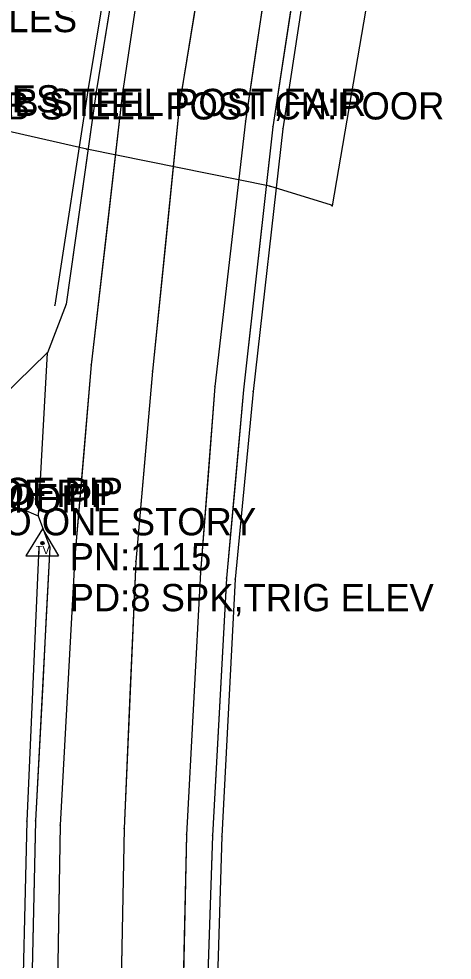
# Model space of a CAD drawing. Extents: x -99999 to 591807, y -99999 to 347168.
# Drawn here: x 591063.4 to 591143, y 322005.6 to 322178.3 of the extents above; entities that cross this region are included whole.
import ezdxf

# ---------------------------------------------------------------- set-up
doc = ezdxf.new("R2010")
doc.units = 0
for name, color, linetype in [('S_BREAKLINE', 7, 'Continuous'), ('S_DRIVEWAY', 7, 'Continuous'), ('S_EDGE_PAVEMENT', 7, 'Continuous'), ('S_FENCE_ANNOT', 7, 'Continuous'), ('S_GRD_PT_SYM', 7, 'Continuous'), ('S_PAVEMENT_CROWN', 7, 'Continuous'), ('S_RDW_PT_SYM', 7, 'Continuous'), ('S_SECONDARY_CTL', 7, 'Continuous'), ('S_SECONDARY_CTL_ANNOT', 7, 'Continuous'), ('S_SHOULDER', 7, 'Continuous'), ('S_SIDE_DRAIN_ANNOT', 7, 'Continuous'), ('S_SURVEY_TEXT_ANNOT', 7, 'Continuous'), ('S_UTILITY_POLE_ANNOT', 7, 'Continuous'), ('S_UTL_PT_SYM', 7, 'Continuous'), ('S_WATER_UTILITIES', 7, 'Continuous')]:
    doc.layers.add(name, color=color, linetype=linetype)

msp = doc.modelspace()

# ---------------------------------------------------------------- linework, layer by layer
at = {"layer": 'S_BREAKLINE'}
for points in [[(591141.79, 322332.97), (591141.12, 322331.79), (591136.59, 322308.68), (591127.43, 322256.21), (591119.53, 322208.24), (591111.89, 322158.15), (591106.46, 322109.92), (591103.16, 322075.48), (591100.72, 322028.3), (591099.37, 321984.38), (591097.36, 321936.25)], [(591093.81, 322271.33), (591084.18, 322214.09), (591076.06, 322165.17), (591070.01, 322125.75)], [(591068.65, 322117.01), (591066.95, 322087.14)], [(591067.08, 322081.38), (591064.9, 322031.1), (591063.85, 321987.78), (591065.77, 321933.53), (591065.95, 321923.68)]]:
    msp.add_lwpolyline(points, dxfattribs=at)
at = {"layer": 'S_DRIVEWAY'}
msp.add_lwpolyline([(591068.65, 322117.01), (591054.64, 322103.44), (591053.56, 322090.23), (591063.83, 322088.44), (591066.95, 322087.12), (591069.12, 322081.36)], dxfattribs=at)
msp.add_lwpolyline([(591068.65, 322117.01), (591054.64, 322103.44), (591053.56, 322090.23), (591063.83, 322088.44), (591066.95, 322087.12), (591069.12, 322081.36)], dxfattribs=at)
at = {"layer": 'S_EDGE_PAVEMENT'}
for points in [[(591155.01, 322516.17), (591143.09, 322467.79), (591137.43, 322444.09), (591127.36, 322400.1), (591119.29, 322363.42), (591113.95, 322339.18), (591109.05, 322315.77), (591098.43, 322263.26), (591089.75, 322213.36), (591082.38, 322164.3), (591076.73, 322114.81), (591073.7, 322079.67), (591071, 322030.35), (591070.29, 321986.98), (591070.69, 321935.66), (591071.05, 321919.08)], [(591177.24, 322510.33), (591165.63, 322463.26), (591159.78, 322438.95), (591149.6, 322395.03), (591141.62, 322358.52), (591136.41, 322334.23), (591131.46, 322310.28), (591121.02, 322257.9), (591112.47, 322209.78), (591105.04, 322159.54), (591099.44, 322110.84), (591096.78, 322076.76), (591094.19, 322028.58), (591093.31, 321985.65), (591093.42, 321935.97), (591093.55, 321920.04)], [(591086.07, 322188.83), (591082.38, 322164.3), (591079.55, 322139.56), (591076.73, 322114.81), (591075.22, 322097.24), (591073.7, 322079.67), (591072.35, 322055.01), (591071, 322030.35), (591070.64, 322008.66), (591070.29, 321986.98), (591070.39, 321974.15), (591070.49, 321961.32), (591070.59, 321948.49), (591070.69, 321935.66), (591071.05, 321919.08)], [(591108.76, 322184.66), (591106.9, 322172.1), (591105.04, 322159.54), (591102.24, 322135.19), (591099.44, 322110.84), (591098.11, 322093.8), (591096.78, 322076.76), (591095.48, 322052.67), (591094.19, 322028.58), (591093.75, 322007.12), (591093.31, 321985.65), (591093.37, 321960.81), (591093.42, 321935.97), (591093.55, 321920.04)]]:
    msp.add_lwpolyline(points, dxfattribs=at)
at = {"layer": 'S_GRD_PT_SYM'}
for points in [[(591076.06, 322165.17), (591076.11, 322165.16), (591076.06, 322165.17), (591076.07, 322165.21), (591076.06, 322165.17), (591076.02, 322165.17), (591076.06, 322165.17), (591076.06, 322165.12)], [(591111.89, 322158.15), (591111.93, 322158.15), (591111.89, 322158.15), (591111.89, 322158.2), (591111.89, 322158.15), (591111.84, 322158.16), (591111.89, 322158.15), (591111.88, 322158.1)], [(591070.01, 322125.75), (591070.06, 322125.74), (591070.01, 322125.75), (591070.02, 322125.79), (591070.01, 322125.75), (591069.96, 322125.75), (591070.01, 322125.75), (591070, 322125.7)], [(591068.65, 322117.01), (591068.7, 322117.01), (591068.65, 322117.01), (591068.65, 322117.06), (591068.65, 322117.01), (591068.6, 322117.02), (591068.65, 322117.01), (591068.65, 322116.96)], [(591106.46, 322109.92), (591106.51, 322109.91), (591106.46, 322109.92), (591106.46, 322109.97), (591106.46, 322109.92), (591106.41, 322109.92), (591106.46, 322109.92), (591106.46, 322109.87)], [(591066.95, 322087.14), (591067, 322087.14), (591066.95, 322087.14), (591066.95, 322087.19), (591066.95, 322087.14), (591066.9, 322087.14), (591066.95, 322087.14), (591066.95, 322087.09)], [(591067.08, 322081.38), (591067.13, 322081.38), (591067.08, 322081.38), (591067.09, 322081.43), (591067.08, 322081.38), (591067.03, 322081.38), (591067.08, 322081.38), (591067.08, 322081.33)], [(591103.16, 322075.48), (591103.21, 322075.48), (591103.16, 322075.48), (591103.16, 322075.53), (591103.16, 322075.48), (591103.11, 322075.48), (591103.16, 322075.48), (591103.16, 322075.43)], [(591064.9, 322031.1), (591064.95, 322031.1), (591064.9, 322031.1), (591064.91, 322031.15), (591064.9, 322031.1), (591064.85, 322031.11), (591064.9, 322031.1), (591064.9, 322031.05)], [(591100.72, 322028.3), (591100.77, 322028.3), (591100.72, 322028.3), (591100.72, 322028.35), (591100.72, 322028.3), (591100.67, 322028.3), (591100.72, 322028.3), (591100.72, 322028.25)]]:
    msp.add_lwpolyline(points, close=True, dxfattribs=at)
at = {"layer": 'S_PAVEMENT_CROWN'}
for points in [[(591166.02, 322513.49), (591154.15, 322465.35), (591148.44, 322441.45), (591138.39, 322397.64), (591130.1, 322360.67), (591124.85, 322336.77), (591119.75, 322312.64), (591109.15, 322260.48), (591100.94, 322212.04), (591092.95, 322162.74), (591087.94, 322113.64), (591084.9, 322078.73), (591082.75, 322029.75), (591081.89, 321986.1), (591081.86, 321935.1), (591082.15, 321919.25)], [(591096.94, 322187.39), (591092.95, 322162.74), (591090.45, 322138.19), (591087.94, 322113.64), (591086.42, 322096.18), (591084.9, 322078.73), (591083.82, 322054.24), (591082.75, 322029.75), (591082.32, 322007.92), (591081.89, 321986.1), (591081.88, 321973.35), (591081.88, 321960.6), (591081.87, 321947.85), (591081.86, 321935.1), (591082.15, 321919.25)]]:
    msp.add_lwpolyline(points, dxfattribs=at)
at = {"layer": 'S_RDW_PT_SYM'}
for points in [[(591077.61, 322164.92), (591077.66, 322164.91), (591077.61, 322164.92), (591077.61, 322164.97), (591077.61, 322164.92), (591077.56, 322164.93), (591077.61, 322164.92), (591077.6, 322164.87)], [(591082.38, 322164.3), (591082.43, 322164.29), (591082.38, 322164.3), (591082.38, 322164.35), (591082.38, 322164.3), (591082.33, 322164.31), (591082.38, 322164.3), (591082.37, 322164.25)], [(591092.95, 322162.74), (591093, 322162.73), (591092.95, 322162.74), (591092.95, 322162.79), (591092.95, 322162.74), (591092.9, 322162.74), (591092.95, 322162.74), (591092.94, 322162.69)], [(591105.04, 322159.54), (591105.09, 322159.54), (591105.04, 322159.54), (591105.05, 322159.59), (591105.04, 322159.54), (591104.99, 322159.55), (591105.04, 322159.54), (591105.04, 322159.5)], [(591110.08, 322158.52), (591110.13, 322158.51), (591110.08, 322158.52), (591110.08, 322158.57), (591110.08, 322158.52), (591110.03, 322158.52), (591110.08, 322158.52), (591110.07, 322158.47)], [(591072.14, 322125.92), (591072.18, 322125.9), (591072.14, 322125.92), (591072.16, 322125.96), (591072.14, 322125.92), (591072.09, 322125.94), (591072.14, 322125.92), (591072.12, 322125.87)], [(591068.66, 322117.04), (591068.7, 322117.03), (591068.66, 322117.04), (591068.67, 322117.09), (591068.66, 322117.04), (591068.61, 322117.06), (591068.66, 322117.04), (591068.64, 322117)], [(591068.65, 322117.01), (591068.68, 322116.98), (591068.65, 322117.01), (591068.69, 322117.05), (591068.65, 322117.01), (591068.62, 322117.05), (591068.65, 322117.01), (591068.61, 322116.98)], [(591076.73, 322114.81), (591076.78, 322114.81), (591076.73, 322114.81), (591076.73, 322114.86), (591076.73, 322114.81), (591076.68, 322114.81), (591076.73, 322114.81), (591076.72, 322114.76)], [(591087.94, 322113.64), (591087.99, 322113.63), (591087.94, 322113.64), (591087.95, 322113.69), (591087.94, 322113.64), (591087.89, 322113.64), (591087.94, 322113.64), (591087.94, 322113.59)], [(591099.44, 322110.84), (591099.49, 322110.84), (591099.44, 322110.84), (591099.45, 322110.89), (591099.44, 322110.84), (591099.39, 322110.84), (591099.44, 322110.84), (591099.44, 322110.79)], [(591104.71, 322110.25), (591104.76, 322110.24), (591104.71, 322110.25), (591104.72, 322110.3), (591104.71, 322110.25), (591104.66, 322110.25), (591104.71, 322110.25), (591104.71, 322110.2)], [(591063.83, 322088.44), (591063.85, 322088.49), (591063.83, 322088.44), (591063.78, 322088.46), (591063.83, 322088.44), (591063.81, 322088.4), (591063.83, 322088.44), (591063.87, 322088.42)], [(591066.95, 322087.12), (591067, 322087.14), (591066.95, 322087.12), (591066.93, 322087.17), (591066.95, 322087.12), (591066.9, 322087.1), (591066.95, 322087.12), (591066.97, 322087.07)], [(591069.12, 322081.38), (591069.17, 322081.38), (591069.12, 322081.38), (591069.13, 322081.43), (591069.12, 322081.38), (591069.07, 322081.39), (591069.12, 322081.38), (591069.12, 322081.33)], [(591069.12, 322081.36), (591069.17, 322081.38), (591069.12, 322081.36), (591069.1, 322081.41), (591069.12, 322081.36), (591069.07, 322081.35), (591069.12, 322081.36), (591069.14, 322081.32)], [(591073.7, 322079.67), (591073.75, 322079.66), (591073.7, 322079.67), (591073.71, 322079.72), (591073.7, 322079.67), (591073.65, 322079.67), (591073.7, 322079.67), (591073.7, 322079.62)], [(591084.9, 322078.73), (591084.95, 322078.73), (591084.9, 322078.73), (591084.9, 322078.78), (591084.9, 322078.73), (591084.85, 322078.73), (591084.9, 322078.73), (591084.9, 322078.68)], [(591096.78, 322076.76), (591096.83, 322076.75), (591096.78, 322076.76), (591096.78, 322076.81), (591096.78, 322076.76), (591096.73, 322076.76), (591096.78, 322076.76), (591096.78, 322076.71)], [(591101.57, 322075.67), (591101.62, 322075.67), (591101.57, 322075.67), (591101.58, 322075.72), (591101.57, 322075.67), (591101.52, 322075.68), (591101.57, 322075.67), (591101.57, 322075.62)], [(591066.47, 322031.16), (591066.52, 322031.16), (591066.47, 322031.16), (591066.47, 322031.21), (591066.47, 322031.16), (591066.42, 322031.16), (591066.47, 322031.16), (591066.47, 322031.11)], [(591071, 322030.35), (591071.05, 322030.34), (591071, 322030.35), (591071, 322030.4), (591071, 322030.35), (591070.95, 322030.35), (591071, 322030.35), (591070.99, 322030.3)], [(591082.75, 322029.75), (591082.8, 322029.75), (591082.75, 322029.75), (591082.75, 322029.8), (591082.75, 322029.75), (591082.7, 322029.75), (591082.75, 322029.75), (591082.75, 322029.7)], [(591094.19, 322028.58), (591094.24, 322028.58), (591094.19, 322028.58), (591094.19, 322028.63), (591094.19, 322028.58), (591094.14, 322028.59), (591094.19, 322028.58), (591094.18, 322028.53)], [(591098.96, 322028.42), (591099.01, 322028.42), (591098.96, 322028.42), (591098.96, 322028.47), (591098.96, 322028.42), (591098.91, 322028.43), (591098.96, 322028.42), (591098.96, 322028.37)]]:
    msp.add_lwpolyline(points, close=True, dxfattribs=at)
at = {"layer": 'S_SECONDARY_CTL'}
for p, q in [((591067.74, 322084.71), (591064.73, 322079.75)), ((591067.74, 322084.71), (591070.69, 322079.75)), ((591064.73, 322079.75), (591070.69, 322079.75))]:
    msp.add_line(p, q, dxfattribs=at)
for radius in [0.311, 0.183, 0.103]:
    msp.add_circle((591067.74, 322082.1), radius, dxfattribs=at)
at = {"layer": 'S_SHOULDER'}
for points in [[(591137.44, 322469.34), (591133.63, 322445.25), (591123.61, 322401.4), (591115.17, 322364.04), (591109.62, 322340), (591104.84, 322316.87), (591100.55, 322301.53), (591098.37, 322297.55), (591094.49, 322275.99), (591096.67, 322271.91), (591095.47, 322264.19), (591085.55, 322213.88), (591077.61, 322164.92), (591072.14, 322125.92), (591068.66, 322117.04)], [(591137.44, 322469.34), (591133.63, 322445.25), (591128.62, 322423.33), (591123.61, 322401.4), (591119.39, 322382.72), (591115.17, 322364.04), (591109.62, 322340), (591104.84, 322316.87), (591100.55, 322301.53), (591098.37, 322297.55), (591094.49, 322275.99), (591096.67, 322271.91), (591095.47, 322264.19), (591092.99, 322251.61), (591090.51, 322239.04), (591088.03, 322226.46), (591085.55, 322213.88), (591081.58, 322189.4), (591077.61, 322164.92), (591074.87, 322145.42), (591072.14, 322125.92), (591068.66, 322117.04)], [(591140.98, 322334.12), (591140.11, 322333.4), (591135.06, 322309.16), (591125.66, 322256.81), (591117.7, 322208.32), (591110.08, 322158.52), (591104.71, 322110.25), (591101.57, 322075.67), (591098.96, 322028.42), (591097.53, 321984.9), (591096.04, 321935.78), (591096.53, 321921.92), (591094.98, 321920.21)], [(591113.89, 322183.42), (591111.98, 322170.97), (591110.08, 322158.52), (591107.39, 322134.38), (591104.71, 322110.25), (591103.14, 322092.96), (591101.57, 322075.67), (591100.27, 322052.05), (591098.96, 322028.42), (591098.25, 322006.66), (591097.53, 321984.9), (591096.79, 321960.34), (591096.04, 321935.78), (591096.53, 321921.92), (591094.98, 321920.21)], [(591069.12, 322081.38), (591066.47, 322031.16), (591065.51, 321987.43), (591066.83, 321935.11), (591068.74, 321922.89), (591069.66, 321919.06)], [(591069.12, 322081.38), (591068.46, 322068.83), (591067.8, 322056.27), (591067.13, 322043.72), (591066.47, 322031.16), (591065.99, 322009.3), (591065.51, 321987.43), (591065.84, 321974.35), (591066.17, 321961.27), (591066.5, 321948.19), (591066.83, 321935.11), (591068.74, 321922.89), (591069.66, 321919.06)]]:
    msp.add_lwpolyline(points, dxfattribs=at)
at = {"layer": 'S_UTL_PT_SYM'}
for points in [[(591075.88, 322154.39), (591075.88, 322154.44), (591075.88, 322154.39), (591075.83, 322154.39), (591075.88, 322154.39), (591075.88, 322154.34), (591075.88, 322154.39), (591075.93, 322154.39)], [(591109.5, 322147.63), (591109.5, 322147.68), (591109.5, 322147.63), (591109.45, 322147.63), (591109.5, 322147.63), (591109.5, 322147.58), (591109.5, 322147.63), (591109.55, 322147.63)], [(591120.85, 322144.09), (591120.85, 322144.14), (591120.85, 322144.09), (591120.8, 322144.09), (591120.85, 322144.09), (591120.85, 322144.04), (591120.85, 322144.09), (591120.9, 322144.09)], [(591120.97, 322143.98), (591120.97, 322144.03), (591120.97, 322143.98), (591120.92, 322143.98), (591120.97, 322143.98), (591120.97, 322143.93), (591120.97, 322143.98), (591121.02, 322143.98)]]:
    msp.add_lwpolyline(points, dxfattribs=at)
at = {"layer": 'S_WATER_UTILITIES'}
for p, q in [((591144.96, 322284.3), (591120.97, 322143.98)), ((591075.88, 322154.39), (591054.1, 322159.37)), ((591109.5, 322147.63), (591075.88, 322154.39)), ((591120.85, 322144.09), (591109.5, 322147.63))]:
    msp.add_line(p, q, dxfattribs=at)

# ---------------------------------------------------------------- texts
at = {"layer": 'S_FENCE_ANNOT'}
for s, p in [('6 BARB STEEL POST,FAIR', (591043.25, 322160.47)), ('4 BARB STEEL POST CN:POOR', (591041.64, 322159.84))]:
    msp.add_text(s, height=5, dxfattribs=at).set_placement(p)
at = {"layer": 'S_SECONDARY_CTL'}
msp.add_text('TV', height=1.5, rotation=360, dxfattribs=at).set_placement((591066.53, 322080.09))
at = {"layer": 'S_SECONDARY_CTL_ANNOT'}
for s, p in [('PN:1115', (591072.74, 322077.1)), ('PD:8 SPK,TRIG ELEV', (591072.74, 322069.6))]:
    msp.add_text(s, height=5, dxfattribs=at).set_placement(p)
at = {"layer": 'S_SIDE_DRAIN_ANNOT'}
for s, p in [('DI:16" TY:RCP CN:30% BTTM OF PI', (590967.9, 322087.96)), ('DI:16" TY:RCP CN:0% BTTM OF PIP', (590969.5, 322088.73)), ('DI:16" TY:RCP CN:0% BTTM OF PIP', (590970.94, 322089.1)), ('DI:16" TY:RCP CN:%FILL BTTM OF ', (590966.69, 322087.7))]:
    msp.add_text(s, height=5, dxfattribs=at).set_placement(p)
at = {"layer": 'S_SURVEY_TEXT_ANNOT'}
msp.add_text('BROKEN ASPH TO ONE STORY', height=5, dxfattribs=at).set_placement((591006.33, 322083.53))
at = {"layer": 'S_UTILITY_POLE_ANNOT'}
for s, p in [('2 POLES', (591046.24, 322175.86)), ('2 WIRES', (591043.54, 322161.13))]:
    msp.add_text(s, height=5, dxfattribs=at).set_placement(p)

doc.saveas('drawing.dxf')
